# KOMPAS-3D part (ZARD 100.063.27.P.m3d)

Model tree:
1. Операция без истории:1
2. Операция без истории:2
3. Операция без истории:3
4. Операция без истории:4
5. Операция без истории:5
6. Операция без истории:6
7. Операция без истории:7
8. Операция без истории:8
9. Операция без истории:9
10. Операция без истории:10
11. Операция без истории:11
12. Операция без истории:12
13. Операция без истории:13
14. Операция без истории:14
15. Операция без истории:15
16. Операция без истории:16
17. Операция без истории:17
18. Операция без истории:18
19. Операция без истории:19
20. Операция без истории:20
21. Операция без истории:21
22. Операция без истории:22
23. Операция без истории:23
24. Операция без истории:24
25. Операция без истории:25
26. Операция без истории:26
27. Операция без истории:27
28. Операция без истории:28
29. Операция без истории:29
30. Операция без истории:30
31. Операция без истории:31
32. Операция без истории:32
33. Операция без истории:33
34. Операция без истории:34
35. Операция без истории:35
36. Операция без истории:36
37. Операция без истории:37
38. Операция без истории:38
39. Операция без истории:39
40. Операция без истории:40
41. Операция без истории:41
42. Операция без истории:42
43. Операция без истории:43
44. Операция без истории:44
45. Операция без истории:45
46. Операция без истории:46
47. Операция без истории:47
48. Операция без истории:48
49. Операция без истории:49
50. Операция без истории:50
51. Операция без истории:51
52. Операция без истории:52
53. Операция без истории:53
54. Операция без истории:54
55. Операция без истории:55
56. Операция без истории:56
57. Операция без истории:57
58. Операция без истории:58
59. Операция без истории:59
60. Операция без истории:60
61. Операция без истории:61
62. Операция без истории:62
63. Операция без истории:63

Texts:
  ЗАРД 100.063.27-ХХ.Р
